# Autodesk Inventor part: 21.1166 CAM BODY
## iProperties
Created: 2007-03
Part Number: 21.1166 CAM BODY
Document SubType Name: Modeling
Designer: Andy Moles
Material: Steel
Mass: 20.4745 g
Surface Area: 20.9331 cm^2
Volume: 2.60821 cm^3
Density: 7.85 g/cm^3
Author: Andy Moles
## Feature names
1. Base1
